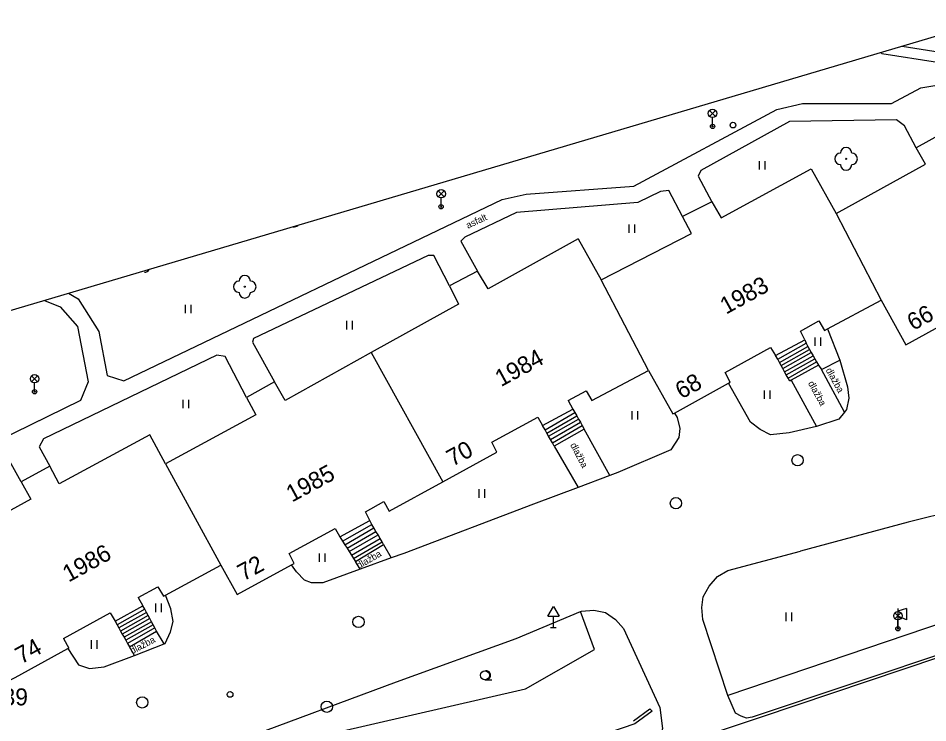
# Model space of a CAD drawing. Extents: x -493753 to -49290, y -1127285 to -112654.
# Drawn here: x -493325.4 to -493245.2, y -1126683.4 to -1126621.3 of the extents above; entities that cross this region are included whole.
import ezdxf

# ---------------------------------------------------------------- set-up
doc = ezdxf.new("R2010")
doc.units = 0
for name, color, linetype in [('Vrstva 1', 7, 'Continuous'), ('Vrstva 10', 7, 'Continuous'), ('Vrstva 11', 7, 'Continuous'), ('Vrstva 21', 7, 'Continuous'), ('Vrstva 22', 7, 'Continuous'), ('Vrstva 25', 7, 'Continuous'), ('Vrstva 27', 7, 'Continuous'), ('Vrstva 31', 7, 'Continuous'), ('Vrstva 33', 7, 'Continuous'), ('Vrstva 34', 7, 'Continuous'), ('Vrstva 36', 7, 'Continuous'), ('Vrstva 40', 7, 'Continuous'), ('Vrstva 43', 7, 'Continuous'), ('Vrstva 44', 7, 'Continuous'), ('Vrstva 5', 7, 'Continuous'), ('Vrstva 60', 7, 'Continuous'), ('Vrstva 63', 7, 'Continuous')]:
    doc.layers.add(name, color=color, linetype=linetype)

msp = doc.modelspace()

# ---------------------------------------------------------------- linework, layer by layer
at = {"layer": 'Vrstva 1'}
msp.add_line((-492950.39, -1126535.73), (-493753.129, -1126773.634), dxfattribs=at)
at = {"layer": 'Vrstva 10'}
for p, q in [((-493323.056, -1126646.175), (-493321.66, -1126646.74)), ((-493321.66, -1126646.74), (-493320.15, -1126648.47)), ((-493320.15, -1126648.47), (-493319.2, -1126653.37)), ((-493254.55, -1126652.27), (-493252.93, -1126651.44)), ((-493254.83, -1126651.88), (-493254.55, -1126652.27)), ((-493319.2, -1126653.37), (-493319.87, -1126655)), ((-493319.87, -1126655), (-493327.8, -1126658.88)), ((-493273.21, -1126661.62), (-493275.47, -1126657.52)), ((-493278.12, -1126659.02), (-493276.01, -1126662.66)), ((-493295.22, -1126669.87), (-493295.63, -1126669.2)), ((-493312.51, -1126676.47), (-493313.17, -1126675.34)), ((-493315.13, -1126677.48), (-493315.56, -1126676.73))]:
    msp.add_line(p, q, dxfattribs=at)
for points in [[(-493245.79, -1126627.42), (-493240.29, -1126626.53), (-493239.34, -1126626.37), (-493238.41, -1126626.21), (-493237.31, -1126626.01), (-493236.18, -1126625.22)], [(-493320.925, -1126645.544), (-493320.09, -1126646.03), (-493318.25, -1126648.91), (-493317.54, -1126652.8), (-493316.07, -1126653.26), (-493282.7, -1126637.29), (-493280.6, -1126636.8), (-493271.11, -1126636.09), (-493258.5, -1126629.34), (-493256.24, -1126628.8), (-493248.38, -1126628.82), (-493245.79, -1126627.42)], [(-493246.2, -1126632.71), (-493247.23, -1126630.79), (-493247.95, -1126630.26), (-493257.38, -1126630.41), (-493265.19, -1126634.72), (-493265.43, -1126635.23), (-493264.22, -1126637.47)], [(-493266.8, -1126638.79), (-493268.02, -1126636.48), (-493268.74, -1126636.56), (-493270.75, -1126637.55), (-493281.44, -1126638.42), (-493286, -1126640.6), (-493286.36, -1126640.94), (-493284.88, -1126643.59)], [(-493287.35, -1126644.9), (-493288.74, -1126642.23), (-493289.22, -1126642.23), (-493304.62, -1126649.54), (-493304.72, -1126649.87), (-493302.77, -1126653.35)], [(-493254.03, -1126648.69), (-493252.93, -1126651.44), (-493252.26, -1126653.79), (-493252.16, -1126654.81), (-493252.35, -1126655.79), (-493252.54, -1126656.02), (-493253.04, -1126656.66), (-493254.99, -1126657.3)], [(-493256.04, -1126649.64), (-493255.92, -1126649.95)], [(-493255.92, -1126649.95), (-493255.77, -1126650.23)], [(-493255.77, -1126650.23), (-493255.61, -1126650.5)], [(-493255.61, -1126650.5), (-493255.46, -1126650.77)], [(-493255.46, -1126650.77), (-493255.3, -1126651.05)], [(-493305.23, -1126654.74), (-493307.12, -1126651.11), (-493307.87, -1126651), (-493323.14, -1126658.39), (-493323.52, -1126659.09), (-493322.58, -1126660.8)], [(-493258.42, -1126651.37), (-493258.6, -1126651.04)], [(-493258.27, -1126651.64), (-493258.42, -1126651.37)], [(-493255.3, -1126651.05), (-493255.15, -1126651.32)], [(-493255.15, -1126651.32), (-493254.99, -1126651.59)], [(-493254.99, -1126651.59), (-493254.83, -1126651.88)], [(-493258.12, -1126651.92), (-493258.27, -1126651.64)], [(-493257.97, -1126652.19), (-493258.12, -1126651.92)], [(-493257.81, -1126652.47), (-493257.97, -1126652.19)], [(-493257.66, -1126652.74), (-493257.81, -1126652.47)], [(-493257.51, -1126653.02), (-493257.66, -1126652.74)], [(-493257.36, -1126653.29), (-493257.51, -1126653.02)], [(-493254.99, -1126657.3), (-493257.4, -1126657.85), (-493259.06, -1126658.02), (-493259.95, -1126657.56), (-493260.82, -1126656.91), (-493262.76, -1126653.48)], [(-493257.24, -1126653.22), (-493257.36, -1126653.29)], [(-493257.24, -1126653.22), (-493254.99, -1126657.3)], [(-493267.51, -1126656.11), (-493267.27, -1126656.51), (-493267.05, -1126657.48), (-493267.12, -1126658.27), (-493267.84, -1126659.36), (-493272.51, -1126661.36), (-493273.21, -1126661.62), (-493276.01, -1126662.66), (-493279.94, -1126664.13), (-493291.39, -1126668.48), (-493292.5, -1126668.88), (-493295.22, -1126669.87), (-493298.51, -1126671.07), (-493299.51, -1126671.07), (-493300.14, -1126670.86), (-493300.85, -1126670.1), (-493301.27, -1126669.5)], [(-493276.48, -1126655.77), (-493276.31, -1126656.07)], [(-493276.31, -1126656.07), (-493276.14, -1126656.35)], [(-493276.14, -1126656.35), (-493275.98, -1126656.64)], [(-493278.93, -1126657.59), (-493279.14, -1126657.21)], [(-493275.98, -1126656.64), (-493275.81, -1126656.92)], [(-493275.81, -1126656.92), (-493275.65, -1126657.21)], [(-493275.65, -1126657.21), (-493275.47, -1126657.52)], [(-493278.77, -1126657.87), (-493278.93, -1126657.59)], [(-493278.61, -1126658.16), (-493278.77, -1126657.87)], [(-493278.44, -1126658.45), (-493278.61, -1126658.16)], [(-493278.28, -1126658.73), (-493278.44, -1126658.45)], [(-493278.12, -1126659.02), (-493278.28, -1126658.73)], [(-493325.1, -1126662.16), (-493326.15, -1126660.31), (-493331.34, -1126660.63), (-493333.05, -1126660.7)], [(-493223.88, -1126659.91), (-493238.39, -1126663.61), (-493246.91, -1126665.74), (-493256.4, -1126668.29)], [(-493197.62, -1126661.66), (-493221.97, -1126669.89), (-493233.95, -1126674), (-493260.66, -1126682.94), (-493261.18, -1126683.01), (-493261.64, -1126682.84), (-493262.13, -1126682.56), (-493262.81, -1126681.03)], [(-493294.2, -1126665.93), (-493294.38, -1126665.58)], [(-493294.01, -1126666.24), (-493294.2, -1126665.93)], [(-493293.83, -1126666.55), (-493294.01, -1126666.24)], [(-493293.65, -1126666.86), (-493293.83, -1126666.55)], [(-493218.86, -1126666.51), (-493219.25, -1126666.66), (-493219.4, -1126666.37), (-493223.58, -1126667.74), (-493245.31, -1126675.07), (-493262.81, -1126681.03)], [(-493297.03, -1126667.02), (-493296.77, -1126667.42)], [(-493296.77, -1126667.42), (-493296.58, -1126667.73)], [(-493293.47, -1126667.17), (-493293.65, -1126666.86)], [(-493293.29, -1126667.48), (-493293.47, -1126667.17)], [(-493293.17, -1126667.69), (-493293.29, -1126667.48)], [(-493296.58, -1126667.73), (-493296.38, -1126668.03)], [(-493296.38, -1126668.03), (-493296.19, -1126668.33)], [(-493296.19, -1126668.33), (-493295.99, -1126668.63)], [(-493293.17, -1126667.69), (-493292.5, -1126668.88)], [(-493262.81, -1126681.03), (-493265.02, -1126674.3), (-493265.11, -1126673.25), (-493265, -1126672.31), (-493264.47, -1126671.37), (-493263.73, -1126670.52), (-493262.81, -1126670), (-493256.4, -1126668.29)], [(-493295.99, -1126668.63), (-493295.8, -1126668.94)], [(-493295.8, -1126668.94), (-493295.63, -1126669.2)], [(-493321, -1126676.87), (-493320.05, -1126678.32), (-493319.09, -1126678.63), (-493317.79, -1126678.5), (-493315.13, -1126677.48), (-493312.51, -1126676.47), (-493312.4, -1126676.43), (-493311.93, -1126675.41), (-493311.71, -1126674.49), (-493311.91, -1126673.36), (-493312.38, -1126672.17)], [(-493314.22, -1126673.41), (-493314.38, -1126673.11)], [(-493314.07, -1126673.69), (-493314.22, -1126673.41)], [(-493313.92, -1126673.96), (-493314.07, -1126673.69)], [(-493313.77, -1126674.24), (-493313.92, -1126673.96)], [(-493305.64, -1126684.87), (-493292.02, -1126679.81), (-493281.46, -1126675.98), (-493275.81, -1126673.62), (-493275.72, -1126673.58), (-493274.63, -1126673.49), (-493273.6, -1126673.69), (-493272.72, -1126674.32), (-493272.01, -1126675.1), (-493268.82, -1126682.06), (-493268.56, -1126683.93), (-493268.9, -1126685.11), (-493269.25, -1126685.64), (-493270.08, -1126686.11), (-493292.56, -1126693.67)], [(-493316.83, -1126674.47), (-493316.66, -1126674.78)], [(-493316.66, -1126674.78), (-493316.5, -1126675.05)], [(-493313.62, -1126674.51), (-493313.77, -1126674.24)], [(-493313.47, -1126674.79), (-493313.62, -1126674.51)], [(-493313.32, -1126675.06), (-493313.47, -1126674.79)], [(-493316.5, -1126675.05), (-493316.35, -1126675.33)], [(-493316.35, -1126675.33), (-493316.2, -1126675.6)], [(-493316.2, -1126675.6), (-493316.04, -1126675.87)], [(-493313.17, -1126675.34), (-493313.32, -1126675.06)], [(-493316.04, -1126675.87), (-493315.89, -1126676.15)], [(-493315.89, -1126676.15), (-493315.73, -1126676.42)], [(-493315.73, -1126676.42), (-493315.56, -1126676.73)], [(-493271.13, -1126683.24), (-493269.69, -1126682.19), (-493269.49, -1126682.39), (-493271, -1126683.52), (-493287.36, -1126689.1)]]:
    msp.add_lwpolyline(points, dxfattribs=at)
at = {"layer": 'Vrstva 11'}
for p, q in [((-493258.42, -1126651.37), (-493255.92, -1126649.95)), ((-493258.27, -1126651.64), (-493255.77, -1126650.23)), ((-493258.12, -1126651.92), (-493255.61, -1126650.5)), ((-493257.97, -1126652.19), (-493255.46, -1126650.77)), ((-493257.81, -1126652.47), (-493255.3, -1126651.05)), ((-493257.66, -1126652.74), (-493255.15, -1126651.32)), ((-493257.51, -1126653.02), (-493254.99, -1126651.59)), ((-493252.54, -1126656.02), (-493254.55, -1126652.27)), ((-493278.93, -1126657.59), (-493276.31, -1126656.07)), ((-493278.77, -1126657.87), (-493276.14, -1126656.35)), ((-493278.61, -1126658.16), (-493275.98, -1126656.64)), ((-493278.44, -1126658.45), (-493275.81, -1126656.92)), ((-493278.28, -1126658.73), (-493275.65, -1126657.21)), ((-493275.47, -1126657.52), (-493278.12, -1126659.02)), ((-493296.77, -1126667.42), (-493294.2, -1126665.93)), ((-493296.58, -1126667.73), (-493294.01, -1126666.24)), ((-493296.38, -1126668.03), (-493293.83, -1126666.55)), ((-493296.19, -1126668.33), (-493293.65, -1126666.86)), ((-493295.99, -1126668.63), (-493293.47, -1126667.17)), ((-493295.8, -1126668.94), (-493293.29, -1126667.48)), ((-493295.63, -1126669.2), (-493293.17, -1126667.69)), ((-493314.22, -1126673.41), (-493316.66, -1126674.78)), ((-493314.07, -1126673.69), (-493316.5, -1126675.05)), ((-493313.92, -1126673.96), (-493316.35, -1126675.33)), ((-493313.77, -1126674.24), (-493316.2, -1126675.6)), ((-493313.62, -1126674.51), (-493316.04, -1126675.87)), ((-493313.47, -1126674.79), (-493315.89, -1126676.15)), ((-493313.32, -1126675.06), (-493315.73, -1126676.42)), ((-493315.56, -1126676.73), (-493313.17, -1126675.34))]:
    msp.add_line(p, q, dxfattribs=at)
for points in [[(-493249.339, -1126624.328), (-493249.23, -1126624.39), (-493244.32, -1126625.18), (-493240.29, -1126626.53)], [(-493247.444, -1126623.767), (-493244.1, -1126624.3), (-493238.41, -1126626.21)], [(-493254.83, -1126651.88), (-493257.24, -1126653.22)], [(-493189.64, -1126659.3), (-493209.67, -1126666.01), (-493225.48, -1126671.35), (-493259.89, -1126682.92), (-493292.6, -1126693.86), (-493334.36, -1126707.98), (-493386.3, -1126725.37), (-493427.21, -1126739.01), (-493434.14, -1126741.64), (-493465.58, -1126752.22), (-493499.11, -1126763.41), (-493496.32, -1126771.61)]]:
    msp.add_lwpolyline(points, dxfattribs=at)
at = {"layer": 'Vrstva 21'}
for p, q in [((-493274.57, -1126676.95), (-493275.81, -1126673.62)), ((-493280.64, -1126680.44), (-493274.57, -1126676.95)), ((-493297.64, -1126684.33), (-493280.64, -1126680.44))]:
    msp.add_line(p, q, dxfattribs=at)
at = {"layer": 'Vrstva 22'}
for centre in [(-493252.39, -1126633.69), (-493305.4, -1126644.97)]:
    msp.add_circle(centre, 0.05, dxfattribs=at)
for centre, start, end in [((-493252.39, -1126633.19), 360, 180), ((-493252.89, -1126633.69), 90, 270), ((-493251.89, -1126633.69), 270, 90), ((-493252.39, -1126634.19), 180, 0), ((-493301.05, -1126639.18), 261.7788, 311.23725), ((-493314.25, -1126643.19), 270, 330.41789), ((-493305.4, -1126644.47), 360, 180), ((-493305.9, -1126644.97), 90, 270), ((-493304.9, -1126644.97), 270, 90), ((-493305.4, -1126645.47), 180, 0)]:
    msp.add_arc(centre, 0.5, start, end, dxfattribs=at)
at = {"layer": 'Vrstva 25'}
msp.add_circle((-493262.36, -1126630.72), 0.25, dxfattribs=at)
at = {"layer": 'Vrstva 27'}
for centre in [(-493256.66, -1126660.27), (-493267.39, -1126664.06), (-493295.37, -1126674.53), (-493314.43, -1126681.62), (-493298.16, -1126682.01)]:
    msp.add_circle(centre, 0.5, dxfattribs=at)
at = {"layer": 'Vrstva 31'}
msp.add_circle((-493306.69, -1126680.92), 0.25, dxfattribs=at)
at = {"layer": 'Vrstva 33'}
for p, q in [((-493264.425, -1126629.415), (-493263.895, -1126629.945)), ((-493264.425, -1126629.945), (-493263.895, -1126629.415)), ((-493264.16, -1126630.83), (-493264.16, -1126630.055)), ((-493288.355, -1126636.505), (-493287.825, -1126637.035)), ((-493288.355, -1126637.035), (-493287.825, -1126636.505)), ((-493288.09, -1126637.92), (-493288.09, -1126637.145)), ((-493324.185, -1126652.815), (-493323.655, -1126653.345)), ((-493324.185, -1126653.345), (-493323.655, -1126652.815)), ((-493323.92, -1126654.23), (-493323.92, -1126653.455)), ((-493248.085, -1126673.715), (-493247.555, -1126674.245)), ((-493248.085, -1126674.245), (-493247.555, -1126673.715)), ((-493247.82, -1126673.33), (-493247.82, -1126675.08)), ((-493247.07, -1126673.33), (-493247.82, -1126673.58)), ((-493247.07, -1126674.33), (-493247.82, -1126674.03)), ((-493247.07, -1126673.33), (-493247.07, -1126674.33)), ((-493247.82, -1126675.13), (-493247.82, -1126674.355))]:
    msp.add_line(p, q, dxfattribs=at)
for centre, radius in [((-493264.16, -1126629.68), 0.375), ((-493264.16, -1126630.83), 0.19), ((-493264.16, -1126630.83), 0.05), ((-493288.09, -1126636.77), 0.375), ((-493288.09, -1126637.92), 0.19), ((-493288.09, -1126637.92), 0.05), ((-493323.92, -1126653.08), 0.375), ((-493323.92, -1126654.23), 0.19), ((-493323.92, -1126654.23), 0.05), ((-493247.82, -1126673.98), 0.375), ((-493247.82, -1126675.13), 0.19), ((-493247.82, -1126675.13), 0.05)]:
    msp.add_circle(centre, radius, dxfattribs=at)
at = {"layer": 'Vrstva 34'}
for p, q in [((-493278.69, -1126674.03), (-493278.19, -1126673.18)), ((-493278.19, -1126673.18), (-493277.69, -1126674.03)), ((-493278.69, -1126674.03), (-493277.69, -1126674.03)), ((-493278.19, -1126675.03), (-493278.19, -1126674.03)), ((-493278.44, -1126675.03), (-493277.94, -1126675.03))]:
    msp.add_line(p, q, dxfattribs=at)
at = {"layer": 'Vrstva 36'}
for p, q in [((-493260.02, -1126634.64), (-493260.02, -1126633.89)), ((-493259.52, -1126634.64), (-493259.52, -1126633.89)), ((-493271.52, -1126640.22), (-493271.52, -1126639.47)), ((-493271.02, -1126640.22), (-493271.02, -1126639.47)), ((-493310.61, -1126647.31), (-493310.61, -1126646.56)), ((-493310.11, -1126647.31), (-493310.11, -1126646.56)), ((-493296.41, -1126648.73), (-493296.41, -1126647.98)), ((-493295.91, -1126648.73), (-493295.91, -1126647.98)), ((-493255.13, -1126650.19), (-493255.13, -1126649.44)), ((-493254.63, -1126650.19), (-493254.63, -1126649.44)), ((-493259.58, -1126654.86), (-493259.58, -1126654.11)), ((-493259.08, -1126654.86), (-493259.08, -1126654.11)), ((-493310.83, -1126655.68), (-493310.83, -1126654.93)), ((-493310.33, -1126655.68), (-493310.33, -1126654.93)), ((-493271.25, -1126656.68), (-493271.25, -1126655.93)), ((-493270.75, -1126656.68), (-493270.75, -1126655.93)), ((-493284.74, -1126663.58), (-493284.74, -1126662.83)), ((-493284.24, -1126663.58), (-493284.24, -1126662.83)), ((-493298.81, -1126669.24), (-493298.81, -1126668.49)), ((-493298.31, -1126669.24), (-493298.31, -1126668.49)), ((-493313.24, -1126673.66), (-493313.24, -1126672.91)), ((-493312.74, -1126673.66), (-493312.74, -1126672.91)), ((-493257.66, -1126674.46), (-493257.66, -1126673.71)), ((-493257.16, -1126674.46), (-493257.16, -1126673.71)), ((-493318.92, -1126676.9), (-493318.92, -1126676.15)), ((-493318.42, -1126676.9), (-493318.42, -1126676.15)), ((-493284.23, -1126679.63), (-493284.13, -1126679.63)), ((-493284.13, -1126679.63), (-493283.63, -1126679.63))]:
    msp.add_line(p, q, dxfattribs=at)
msp.add_circle((-493284.23, -1126679.23), 0.4, dxfattribs=at)
msp.add_arc((-493284.13, -1126679.23), 0.4, 259.69515, 97.18076, dxfattribs=at)
at = {"layer": 'Vrstva 5'}
for p, q in [((-493243.71, -1126631.33), (-493246.2, -1126632.71)), ((-493245.4, -1126634.15), (-493246.2, -1126632.71)), ((-493264.22, -1126637.47), (-493266.8, -1126638.79)), ((-493253.27, -1126638.51), (-493249.29, -1126646.16)), ((-493266.03, -1126640.29), (-493266.8, -1126638.79)), ((-493273.99, -1126644.36), (-493266.03, -1126640.29)), ((-493276, -1126640.76), (-493283.94, -1126645.17)), ((-493284.88, -1126643.59), (-493287.35, -1126644.9)), ((-493283.94, -1126645.17), (-493284.88, -1126643.59)), ((-493269.82, -1126652.35), (-493273.99, -1126644.36)), ((-493287.35, -1126644.9), (-493286.57, -1126646.5)), ((-493249.29, -1126646.16), (-493247.13, -1126650.1)), ((-493247.13, -1126650.1), (-493242.24, -1126647.41)), ((-493256.42, -1126648.9), (-493254.8, -1126647.99)), ((-493254.8, -1126647.99), (-493254.29, -1126648.83)), ((-493256.04, -1126649.64), (-493256.42, -1126648.9)), ((-493258.6, -1126651.04), (-493256.04, -1126649.64)), ((-493294.26, -1126650.78), (-493287.93, -1126662.17)), ((-493263.05, -1126652.53), (-493259.04, -1126650.32)), ((-493259.04, -1126650.32), (-493258.6, -1126651.04)), ((-493274.8, -1126655), (-493269.82, -1126652.35)), ((-493269.82, -1126652.35), (-493267.66, -1126656.19)), ((-493262.6, -1126653.39), (-493263.05, -1126652.53)), ((-493302.77, -1126653.35), (-493305.23, -1126654.74)), ((-493301.85, -1126655), (-493302.77, -1126653.35)), ((-493305.23, -1126654.74), (-493304.43, -1126656.28)), ((-493276.9, -1126655), (-493275.31, -1126654.14)), ((-493275.31, -1126654.14), (-493274.8, -1126655)), ((-493276.9, -1126655), (-493276.48, -1126655.77)), ((-493304.43, -1126656.28), (-493312.39, -1126660.59)), ((-493279.14, -1126657.21), (-493276.48, -1126655.77)), ((-493283.63, -1126658.69), (-493279.56, -1126656.47)), ((-493279.56, -1126656.47), (-493279.14, -1126657.21)), ((-493313.77, -1126658.03), (-493321.75, -1126662.35)), ((-493312.39, -1126660.59), (-493313.77, -1126658.03)), ((-493283.18, -1126659.57), (-493283.63, -1126658.69)), ((-493322.58, -1126660.8), (-493325.1, -1126662.16)), ((-493321.75, -1126662.35), (-493322.58, -1126660.8)), ((-493312.39, -1126660.59), (-493307.5, -1126669.51)), ((-493325.1, -1126662.16), (-493324.27, -1126663.71)), ((-493324.27, -1126663.71), (-493332.24, -1126668.11)), ((-493294.76, -1126664.81), (-493293.14, -1126663.92)), ((-493293.14, -1126663.92), (-493292.67, -1126664.77)), ((-493294.38, -1126665.58), (-493294.76, -1126664.81)), ((-493297.03, -1126667.02), (-493294.38, -1126665.58)), ((-493301.49, -1126668.5), (-493297.43, -1126666.29)), ((-493297.43, -1126666.29), (-493297.03, -1126667.02)), ((-493301.05, -1126669.38), (-493301.49, -1126668.5)), ((-493307.5, -1126669.51), (-493306.08, -1126672.12)), ((-493314.79, -1126672.38), (-493313.06, -1126671.42)), ((-493313.06, -1126671.42), (-493312.56, -1126672.27)), ((-493314.79, -1126672.38), (-493314.38, -1126673.11)), ((-493316.83, -1126674.47), (-493314.38, -1126673.11)), ((-493321.38, -1126676), (-493317.27, -1126673.73)), ((-493317.27, -1126673.73), (-493316.83, -1126674.47)), ((-493321.38, -1126676), (-493320.92, -1126676.83))]:
    msp.add_line(p, q, dxfattribs=at)
for points in [[(-493264.22, -1126637.47), (-493263.4, -1126638.89), (-493255.47, -1126634.56), (-493253.27, -1126638.51)], [(-493253.27, -1126638.51), (-493245.4, -1126634.15)], [(-493276, -1126640.76), (-493273.99, -1126644.36)], [(-493286.57, -1126646.5), (-493294.26, -1126650.78)], [(-493254.29, -1126648.83), (-493254.03, -1126648.69), (-493249.29, -1126646.16)], [(-493294.26, -1126650.78), (-493301.85, -1126655)], [(-493267.66, -1126656.19), (-493267.51, -1126656.11), (-493262.76, -1126653.48), (-493262.6, -1126653.39)], [(-493287.93, -1126662.17), (-493283.18, -1126659.57)], [(-493292.67, -1126664.77), (-493287.93, -1126662.17)], [(-493312.56, -1126672.27), (-493312.38, -1126672.17), (-493307.5, -1126669.51)], [(-493306.08, -1126672.12), (-493301.27, -1126669.5), (-493301.05, -1126669.38)], [(-493325.98, -1126679.62), (-493325.64, -1126679.43), (-493321, -1126676.87), (-493320.92, -1126676.83)]]:
    msp.add_lwpolyline(points, dxfattribs=at)
at = {"layer": 'Vrstva 60'}
msp.add_line((-493125, -1126587.478), (-493750, -1126772.707), dxfattribs=at)

# ---------------------------------------------------------------- texts
at = {"layer": 'Vrstva 40'}
for s, rotation, p in [('asfalt', 25.16917, (-493285.724, -1126639.864)), ('dlažba', 299.00679, (-493254.208, -1126652.321)), ('dlažba', 299.00679, (-493255.768, -1126653.481)), ('dlažba', 297.4231, (-493276.73, -1126658.916)), ('dlažba', 29.8611, (-493295.336, -1126669.863)), ('dlažba', 27.92169, (-493315.316, -1126677.389))]:
    msp.add_text(s, height=0.6, rotation=rotation, dxfattribs=at).set_placement(p)
at = {"layer": 'Vrstva 43'}
for s, rotation, p in [('1983', 28.86013, (-493262.972, -1126647.441)), ('1984', 28.61046, (-493282.812, -1126653.831)), ('1985', 28.51555, (-493301.233, -1126664.01)), ('1986', 28.86963, (-493320.931, -1126671.064))]:
    msp.add_text(s, height=1.5, rotation=rotation, dxfattribs=at).set_placement(p)
at = {"layer": 'Vrstva 44'}
for s, rotation, p in [('66', 28.97413, (-493246.48, -1126648.878)), ('68', 28.95837, (-493266.911, -1126654.915)), ('70', 28.72401, (-493287.087, -1126660.859)), ('72', 28.57853, (-493305.516, -1126670.96)), ('74', 28.87161, (-493325.1, -1126678.281))]:
    msp.add_text(s, height=1.5, rotation=rotation, dxfattribs=at).set_placement(p)
at = {"layer": 'Vrstva 63'}
msp.add_text(' 5239', height=1.5, dxfattribs=at).set_placement((-493329.53, -1126681.89))

doc.saveas('drawing.dxf')
